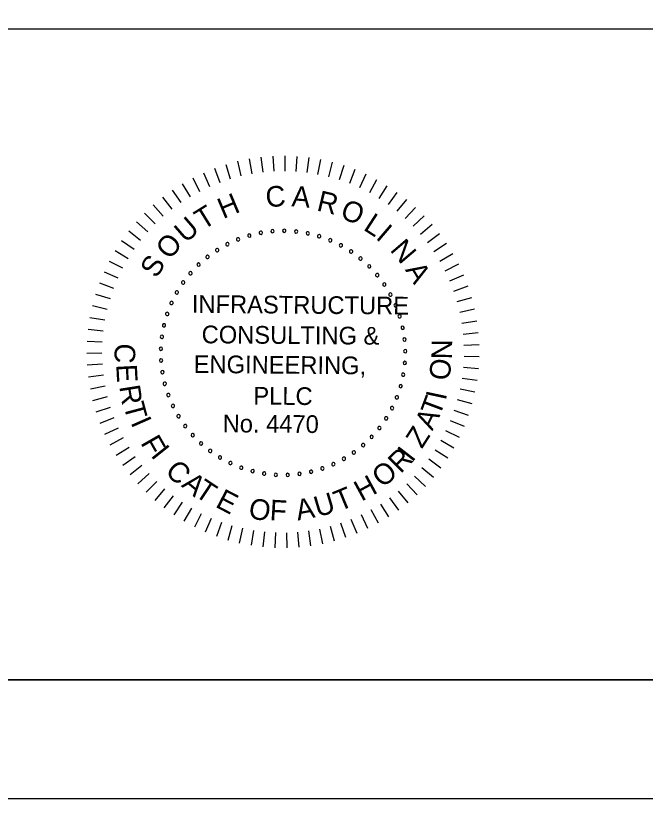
# Model space of a CAD drawing. Extents: x -125.5 to -89.4, y -5.1 to 16.9.
# Drawn here: x -100.328 to -97.671, y -5.066 to -1.76 of the extents above; entities that cross this region are included whole.
import ezdxf

# ---------------------------------------------------------------- set-up
doc = ezdxf.new("R2010")
doc.units = 0
for name, color, linetype in [('BR_BORDER LINES', 7, 'Continuous'), ('BR_TABLE LINES', 7, 'Continuous'), ('BR_TEXT', 7, 'Continuous'), ('Level 31', 7, 'Continuous')]:
    doc.layers.add(name, color=color, linetype=linetype)

msp = doc.modelspace()

# ---------------------------------------------------------------- linework, layer by layer
at = {"layer": 'BR_BORDER LINES'}
for p, q in [((-102.8989, -1.8161), (-97.5337, -1.8161)), ((-123.6994, -4.5662), (-90.0334, -4.5662))]:
    msp.add_line(p, q, dxfattribs=at)
at = {"layer": 'BR_TABLE LINES'}
msp.add_lwpolyline([(-123.6994, 16.4338), (-90.0334, 16.4338), (-90.0334, -4.5662), (-123.6994, -4.5662)], close=True, dxfattribs=at)
at = {"layer": 'BR_TEXT'}
for p, q in [((-99.3925, -2.3754), (-99.3776, -2.4373)), ((-99.343, -2.3651), (-99.332, -2.4278)), ((-99.2931, -2.3579), (-99.2858, -2.4212)), ((-99.2427, -2.3538), (-99.2394, -2.4174)), ((-99.1923, -2.3527), (-99.1928, -2.4164)), ((-99.1418, -2.3548), (-99.1462, -2.4183)), ((-99.0916, -2.3599), (-99.0999, -2.423)), ((-99.0418, -2.368), (-99.0539, -2.4305)), ((-98.9925, -2.3792), (-99.0084, -2.4408)), ((-99.489, -2.4048), (-99.4667, -2.4644)), ((-99.4412, -2.3886), (-99.4226, -2.4495)), ((-98.9441, -2.3933), (-98.9637, -2.4539)), ((-98.8966, -2.4104), (-98.9199, -2.4696)), ((-99.5813, -2.4457), (-99.5519, -2.5022)), ((-99.5358, -2.4238), (-99.5099, -2.482)), ((-98.8502, -2.4303), (-98.877, -2.488)), ((-99.6253, -2.4703), (-99.5926, -2.5249)), ((-98.8051, -2.453), (-98.8354, -2.509)), ((-98.7615, -2.4785), (-98.7952, -2.5325)), ((-99.6678, -2.4975), (-99.6318, -2.55)), ((-98.7195, -2.5065), (-98.7564, -2.5584)), ((-99.7086, -2.5273), (-99.6694, -2.5775)), ((-98.6793, -2.5371), (-98.7193, -2.5866)), ((-99.7475, -2.5595), (-99.7053, -2.6072)), ((-98.6411, -2.57), (-98.684, -2.617)), ((-99.7843, -2.5941), (-99.7393, -2.6391)), ((-98.6049, -2.6052), (-98.6506, -2.6495)), ((-99.819, -2.6308), (-99.7713, -2.673)), ((-98.571, -2.6426), (-98.6193, -2.684)), ((-99.8513, -2.6695), (-99.8012, -2.7087)), ((-99.8813, -2.7102), (-99.8288, -2.7463)), ((-98.5393, -2.6819), (-98.5901, -2.7204)), ((-98.5102, -2.7232), (-98.5632, -2.7584)), ((-99.9087, -2.7526), (-99.8541, -2.7854)), ((-98.4836, -2.7661), (-98.5387, -2.798)), ((-99.9334, -2.7965), (-99.877, -2.826)), ((-99.9555, -2.842), (-99.8973, -2.8679)), ((-98.4597, -2.8105), (-98.5166, -2.839)), ((-98.4385, -2.8563), (-98.497, -2.8813)), ((-99.9747, -2.8886), (-99.9151, -2.911)), ((-98.4202, -2.9034), (-98.4801, -2.9248)), ((-99.991, -2.9364), (-99.9302, -2.9551)), ((-98.4047, -2.9514), (-98.4659, -2.9691)), ((-100.0044, -2.9851), (-99.9426, -3)), ((-98.3922, -3.0004), (-98.4544, -3.0143)), ((-100.0149, -3.0345), (-99.9522, -3.0456)), ((-98.3828, -3.05), (-98.4456, -3.0601)), ((-100.0222, -3.0844), (-99.959, -3.0917)), ((-98.3763, -3.1), (-98.4397, -3.1063)), ((-100.0266, -3.1347), (-99.963, -3.1382)), ((-98.373, -3.1504), (-98.4366, -3.1528)), ((-100.0278, -3.1852), (-99.9641, -3.1847)), ((-98.3727, -3.2009), (-98.4363, -3.1994)), ((-100.026, -3.2356), (-99.9625, -3.2313)), ((-98.3755, -3.2513), (-98.4389, -3.2459)), ((-100.0211, -3.2859), (-99.9579, -3.2777)), ((-98.3813, -3.3014), (-98.4443, -3.2922)), ((-100.0131, -3.3357), (-99.9506, -3.3237)), ((-98.3902, -3.3511), (-98.4525, -3.3381)), ((-100.0021, -3.385), (-99.9405, -3.3692)), ((-98.4021, -3.4002), (-98.4635, -3.3834)), ((-99.9882, -3.4335), (-99.9276, -3.414)), ((-98.417, -3.4484), (-98.4773, -3.4279)), ((-99.9713, -3.4811), (-99.912, -3.4579)), ((-99.9515, -3.5276), (-99.8937, -3.5008)), ((-98.4348, -3.4957), (-98.4937, -3.4715)), ((-98.4554, -3.5417), (-98.5128, -3.514)), ((-99.929, -3.5727), (-99.8729, -3.5425)), ((-98.4789, -3.5865), (-98.5344, -3.5553)), ((-99.9037, -3.6164), (-99.8496, -3.5828)), ((-98.505, -3.6297), (-98.5585, -3.5952)), ((-99.8758, -3.6585), (-99.8239, -3.6217)), ((-98.5336, -3.6712), (-98.5849, -3.6335)), ((-99.8454, -3.6988), (-99.7958, -3.6589)), ((-99.8126, -3.7372), (-99.7655, -3.6943)), ((-98.5648, -3.7109), (-98.6137, -3.6702)), ((-99.7775, -3.7735), (-99.7331, -3.7278)), ((-98.5983, -3.7487), (-98.6447, -3.705)), ((-99.7403, -3.8076), (-99.6988, -3.7593)), ((-98.672, -3.8177), (-98.7126, -3.7687)), ((-98.6341, -3.7843), (-98.6777, -3.7379)), ((-99.701, -3.8393), (-99.6626, -3.7886)), ((-98.7118, -3.8487), (-98.7494, -3.7974)), ((-99.6599, -3.8687), (-99.6246, -3.8157)), ((-98.7534, -3.8772), (-98.7879, -3.8237)), ((-99.6171, -3.8954), (-99.5851, -3.8404)), ((-99.5728, -3.9195), (-99.5442, -3.8626)), ((-98.7967, -3.9032), (-98.8278, -3.8476)), ((-99.527, -3.9408), (-99.5019, -3.8823)), ((-99.48, -3.9594), (-99.4586, -3.8994)), ((-98.8877, -3.9469), (-98.9118, -3.888)), ((-98.8416, -3.9264), (-98.8692, -3.8691)), ((-99.432, -3.975), (-99.4143, -3.9138)), ((-99.3832, -3.9876), (-99.3692, -3.9255)), ((-99.0324, -3.991), (-99.0454, -3.9286)), ((-98.9833, -3.9792), (-99.0001, -3.9178)), ((-98.935, -3.9645), (-98.9555, -3.9042)), ((-99.3336, -3.9973), (-99.3234, -3.9344)), ((-99.2836, -4.0039), (-99.2772, -3.9406)), ((-99.2332, -4.0075), (-99.2307, -3.9438)), ((-99.1827, -4.0079), (-99.1841, -3.9443)), ((-99.1323, -4.0053), (-99.1376, -3.9419)), ((-99.0821, -3.9997), (-99.0913, -3.9367))]:
    msp.add_line(p, q, dxfattribs=at)
for centre, start, end in [((-99.2939, -2.6775), 10.6038, 190.6038), ((-99.2939, -2.6775), 190.6038, 10.6038), ((-99.2445, -2.6708), 5.0653, 185.0653), ((-99.2445, -2.6708), 185.0653, 5.0653), ((-99.1947, -2.6689), 359.5268, 179.5268), ((-99.1947, -2.6689), 179.5268, 359.5268), ((-99.145, -2.6718), 173.9884, 353.9884), ((-99.145, -2.6718), 353.9884, 173.9884), ((-99.0957, -2.6795), 348.4499, 168.4499), ((-99.3896, -2.705), 21.6807, 201.6807), ((-99.3896, -2.705), 201.6807, 21.6807), ((-99.3424, -2.6889), 16.1422, 196.1422), ((-99.3424, -2.6889), 196.1422, 16.1422), ((-99.0957, -2.6795), 168.4499, 348.4499), ((-99.0475, -2.6919), 162.9114, 342.9114), ((-99.0475, -2.6919), 342.9114, 162.9114), ((-99.0006, -2.709), 157.373, 337.373), ((-99.0006, -2.709), 337.373, 157.373), ((-99.4782, -2.7503), 32.7576, 212.7576), ((-99.435, -2.7255), 27.2191, 207.2191), ((-99.435, -2.7255), 207.2191, 27.2191), ((-98.9557, -2.7304), 151.8345, 331.8345), ((-98.9557, -2.7304), 331.8345, 151.8345), ((-99.5188, -2.7792), 38.2961, 218.2961), ((-99.5188, -2.7792), 218.2961, 38.2961), ((-99.4782, -2.7503), 212.7576, 32.7576), ((-98.913, -2.7561), 146.2961, 326.2961), ((-98.913, -2.7561), 326.2961, 146.2961), ((-99.5564, -2.8119), 43.8345, 223.8345), ((-99.5564, -2.8119), 223.8345, 43.8345), ((-98.873, -2.7858), 140.7576, 320.7576), ((-98.873, -2.7858), 320.7576, 140.7576), ((-99.5907, -2.848), 49.373, 229.373), ((-99.5907, -2.848), 229.373, 49.373), ((-98.836, -2.8192), 135.2191, 315.2191), ((-98.836, -2.8192), 315.2191, 135.2191), ((-98.8024, -2.8561), 129.6807, 309.6807), ((-98.8024, -2.8561), 309.6807, 129.6807), ((-99.6214, -2.8873), 54.9114, 234.9114), ((-99.6214, -2.8873), 234.9114, 54.9114), ((-98.7726, -2.896), 124.1422, 304.1422), ((-98.7726, -2.896), 304.1422, 124.1422), ((-99.6481, -2.9293), 60.4499, 240.4499), ((-99.6481, -2.9293), 240.4499, 60.4499), ((-98.7467, -2.9386), 118.6038, 298.6038), ((-98.7467, -2.9386), 298.6038, 118.6038), ((-99.6706, -2.9738), 65.9884, 245.9884), ((-99.6706, -2.9738), 245.9884, 65.9884), ((-98.7251, -2.9835), 113.0653, 293.0653), ((-98.7251, -2.9835), 293.0653, 113.0653), ((-99.6888, -3.0202), 71.5268, 251.5268), ((-99.6888, -3.0202), 251.5268, 71.5268), ((-98.7079, -3.0302), 107.5268, 287.5268), ((-98.7079, -3.0302), 287.5268, 107.5268), ((-99.7024, -3.0681), 77.0653, 257.0653), ((-99.7024, -3.0681), 257.0653, 77.0653), ((-98.6953, -3.0785), 101.9884, 281.9884), ((-98.6953, -3.0785), 281.9884, 101.9884), ((-99.7113, -3.1172), 82.6038, 262.6038), ((-99.7113, -3.1172), 262.6038, 82.6038), ((-98.6874, -3.1277), 96.4499, 276.4499), ((-98.6874, -3.1277), 276.4499, 96.4499), ((-99.7154, -3.1668), 88.1422, 268.1422), ((-99.7154, -3.1668), 268.1422, 88.1422), ((-98.6843, -3.1774), 90.9114, 270.9114), ((-98.6843, -3.1774), 270.9114, 90.9114), ((-99.7147, -3.2167), 93.6807, 273.6807), ((-99.7147, -3.2167), 273.6807, 93.6807), ((-98.686, -3.2272), 85.373, 265.373), ((-98.686, -3.2272), 265.373, 85.373), ((-99.7092, -3.2662), 99.2191, 279.2191), ((-99.7092, -3.2662), 279.2191, 99.2191), ((-98.6926, -3.2766), 79.8345, 259.8345), ((-98.6926, -3.2766), 259.8345, 79.8345), ((-99.6989, -3.3149), 104.7576, 284.7576), ((-99.6989, -3.3149), 284.7576, 104.7576), ((-98.7038, -3.3251), 74.2961, 254.2961), ((-98.7038, -3.3251), 254.2961, 74.2961), ((-99.684, -3.3625), 110.2961, 290.2961), ((-99.684, -3.3625), 290.2961, 110.2961), ((-98.7197, -3.3724), 68.7576, 248.7576), ((-98.7197, -3.3724), 248.7576, 68.7576), ((-99.6646, -3.4084), 115.8345, 295.8345), ((-99.6646, -3.4084), 295.8345, 115.8345), ((-98.7401, -3.4178), 63.2191, 243.2191), ((-98.7401, -3.4178), 243.2191, 63.2191), ((-99.6408, -3.4522), 121.373, 301.373), ((-99.6408, -3.4522), 301.373, 121.373), ((-98.7647, -3.4611), 57.6807, 237.6807), ((-98.7647, -3.4611), 237.6807, 57.6807), ((-99.6129, -3.4935), 126.9114, 306.9114), ((-99.6129, -3.4935), 306.9114, 126.9114), ((-98.7934, -3.5019), 52.1422, 232.1422), ((-98.7934, -3.5019), 232.1422, 52.1422), ((-99.5812, -3.5319), 132.4499, 312.4499), ((-99.5812, -3.5319), 312.4499, 132.4499), ((-98.826, -3.5396), 46.6038, 226.6038), ((-98.826, -3.5396), 226.6038, 46.6038), ((-99.5459, -3.5671), 137.9884, 317.9884), ((-99.5459, -3.5671), 317.9884, 137.9884), ((-98.862, -3.5741), 41.0653, 221.0653), ((-98.862, -3.5741), 221.0653, 41.0653), ((-99.5074, -3.5987), 143.5268, 323.5268), ((-99.5074, -3.5987), 323.5268, 143.5268), ((-98.9012, -3.6049), 35.5268, 215.5268), ((-98.9012, -3.6049), 215.5268, 35.5268), ((-99.466, -3.6264), 149.0653, 329.0653), ((-99.466, -3.6264), 329.0653, 149.0653), ((-98.9431, -3.6317), 29.9884, 209.9884), ((-98.9431, -3.6317), 209.9884, 29.9884), ((-99.4221, -3.65), 154.6038, 334.6038), ((-99.4221, -3.65), 334.6038, 154.6038), ((-99.3761, -3.6693), 160.1422, 340.1422), ((-99.3761, -3.6693), 340.1422, 160.1422), ((-99.0338, -3.6728), 18.9114, 198.9114), ((-98.9875, -3.6545), 24.4499, 204.4499), ((-98.9875, -3.6545), 204.4499, 24.4499), ((-99.3285, -3.684), 165.6807, 345.6807), ((-99.3285, -3.684), 345.6807, 165.6807), ((-99.2797, -3.6941), 351.2191, 171.2191), ((-99.2797, -3.6941), 171.2191, 351.2191), ((-99.2302, -3.6994), 356.7576, 176.7576), ((-99.2302, -3.6994), 176.7576, 356.7576), ((-99.1803, -3.6999), 2.2961, 182.2961), ((-99.1803, -3.6999), 182.2961, 2.2961), ((-99.1307, -3.6956), 7.8345, 187.8345), ((-99.1307, -3.6956), 187.8345, 7.8345), ((-99.0817, -3.6865), 13.373, 193.373), ((-99.0817, -3.6865), 193.373, 13.373), ((-99.0338, -3.6728), 198.9114, 18.9114)]:
    msp.add_arc(centre, 0.00701, start, end, dxfattribs=at)
at = {"layer": 'Level 31'}
msp.add_lwpolyline([(-125.5328, 16.9339), (-125.5328, -5.0661), (-89.5328, -5.0661), (-89.5328, 16.9339)], dxfattribs=at)

# ---------------------------------------------------------------- texts
at = {"layer": 'BR_TEXT'}
for s, height, rotation, p in [('C', 0.0872, 4.7281, (-99.2702, -2.5703)), ('H', 0.0872, 22.7882, (-99.453, -2.6197)), ('A', 0.0872, 355.6981, (-99.1657, -2.5654)), ('R', 0.0872, 346.6681, (-99.0615, -2.5824)), ('O', 0.0872, 337.638, (-98.9637, -2.6122)), ('T', 0.0872, 31.8182, (-99.5379, -2.6674)), ('U', 0.0872, 40.8482, (-99.6112, -2.7235)), ('L', 0.0872, 327.108, (-98.8649, -2.6626)), ('I', 0.0872, 319.578, (-98.8123, -2.7005)), ('O', 0.0872, 49.8782, (-99.6782, -2.7945)), ('N', 0.0872, 310.548, (-98.7515, -2.7512)), ('S', 0.0872, 58.9083, (-99.7336, -2.8727)), ('A', 0.0872, 301.5179, (-98.6864, -2.8336)), ('INFRASTRUCTURE', 0.074771, 359.5268, (-99.585, -3.0152)), ('CONSULTING &', 0.074771, 359.5268, (-99.5437, -3.1438)), ('N', 0.0872, 89.2085, (-98.4872, -3.2124)), ('C', 0.0872, 267.025, (-99.9086, -3.1426)), ('ENGINEERING,', 0.074771, 359.5268, (-99.5773, -3.2693)), ('E', 0.0872, 273.025, (-99.9042, -3.2342)), ('O', 0.0872, 83.2085, (-98.4982, -3.3038)), ('R', 0.0872, 279.025, (-99.8914, -3.3265)), ('PLLC', 0.07477, 359.5268, (-99.3256, -3.4028)), ('T', 0.0872, 69.3954, (-98.5394, -3.4556)), ('I', 0.0872, 77.9093, (-98.5137, -3.3881)), ('T', 0.0872, 285.025, (-99.874, -3.4053)), ('A', 0.0872, 63.3954, (-98.5702, -3.516)), ('I', 0.0872, 293.7713, (-99.8443, -3.4784)), ('No. 4470', 0.07477, 359.5268, (-99.4551, -3.5197)), ('Z', 0.0872, 57.3954, (-98.6141, -3.5923)), ('F', 0.0872, 299.7713, (-99.8031, -3.5644)), ('I', 0.0872, 308.5268, (-99.761, -3.6183)), ('R', 0.0872, 44.5268, (-98.7045, -3.6973)), ('I', 0.0872, 52.3339, (-98.6551, -3.65)), ('C', 0.0872, 314.5268, (-99.7017, -3.6884)), ('O', 0.0872, 38.5268, (-98.7811, -3.7572)), ('A', 0.0872, 320.5268, (-99.6325, -3.747)), ('H', 0.0872, 28.5268, (-98.8692, -3.8132)), ('T', 0.0872, 326.5268, (-99.5781, -3.7855)), ('E', 0.0872, 332.5268, (-99.4895, -3.8332)), ('T', 0.0872, 22.5268, (-98.9624, -3.855)), ('O', 0.0872, 350.5268, (-99.3494, -3.8821)), ('A', 0.0872, 10.5268, (-99.138, -3.8929)), ('U', 0.0872, 16.5268, (-99.0541, -3.8794)), ('F', 0.0872, 356.5268, (-99.2579, -3.8912))]:
    msp.add_text(s, height=height, rotation=rotation, dxfattribs=at).set_placement(p)

doc.saveas('drawing.dxf')
